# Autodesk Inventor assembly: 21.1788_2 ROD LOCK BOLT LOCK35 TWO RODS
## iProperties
Created: 2007-03
Part Number: 21.1788_2 ROD LOCK BOLT LOCK35 TWO RODS
Document SubType Name: Assembly
Designer: Andy Moles
Author: Andy Moles
